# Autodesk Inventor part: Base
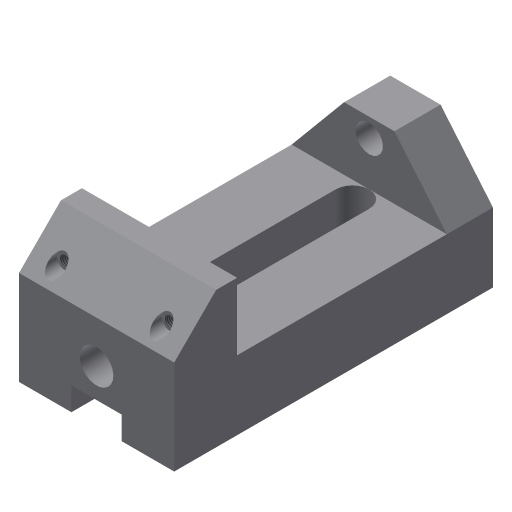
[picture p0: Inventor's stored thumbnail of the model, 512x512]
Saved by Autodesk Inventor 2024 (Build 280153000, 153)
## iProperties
Shininess: 77.0
Length Units: 11269
Angle Units: 11279
Time Units: 11290
Mass Units: 11283
Length Display Precision: 3
Angle Display Precision: 2
Created: 2002-02
Part Number: Base
Document SubType Name: Modeling
Designer: ***
Density: 1 g/cm^3
Material: Generic
Appearance: Default
Density: 0.0
Volumn: 0.0
Area: 0.0
PropertySet Name: Model Information
Control State: 0
Master: False
Checked Out: False
Author: ***
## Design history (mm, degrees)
sketch "Sketch2"
  geometry: L1 (-63.961, -4.254)-(-63.961, -37.254); L2 (-63.961, -37.254)-(88.039, -37.254); L3 (88.039, -37.254)-(88.039, 7.746); L4 (88.039, 7.746)-(68.039, 27.746); L5 (68.039, 27.746)-(58.039, 27.746); L6 (58.039, 27.746)-(58.039, -4.254); L7 (58.039, -4.254)-(-63.961, -4.254)
  constraints: 14 end point, 4 parallel, 1 perpendicular, 1 vertical
  dimensions: "d7" = 10 distance of L4.end L5.end; "d8" = 135 deg angle of L3 L4; "d9" = 33 distance of L1.start L1.end; "d10" = 152 distance of L1.end L2.end; "d11" = 65 distance between parallel lines of L5 L2; "d21" = 30 distance between parallel lines of L3 L6
extrude "Extrusion1" new body sketch "Sketch2" stored distance "d13" = 74; taper "d14" = 0 deg
sketch "Sketch3"
  geometry: L1 (0, 74)-(0, 0) reference; L2 (0, 0)-(-30, 25); L3 (-30, 25)-(-30, 49); L4 (-30, 49)-(0, 74); C1 r 6.5 at (-21, 37)
  constraints: 6 end point, 1 centre point, 1 equal length, 1 parallel
  dimensions: "d15" = 24 distance of L2.end L3.end; "d16" = 30 distance between parallel lines of L3 L1; "d17" = 13 diameter of C1; "d18" = 9 distance from line of L3 C1.centre
extrude "Extrusion2" join sketch "Sketch3" distance "d19" = 22; taper "d20" = 0 deg
sketch "Sketch4"
  geometry: L1 (0, 0)-(0, 74) reference; L2 (0, 0)-(45, 0) reference; C1 r 8 at (25, 37)
  constraints: 1 centre point
  dimensions: "d22" = 16 diameter of C1; "d23" = 25 distance from line of L1 C1.centre; "d24" = 37 distance from line of L2 C1.centre
extrude "Extrusion3" cut sketch "Sketch4" distance "d25" = 13; taper "d26" = 0 deg
sketch "Sketch5"
  geometry: L1 (45, 74)-(0, 74) reference; L2 (65, 0)-(65, 74) reference; 1 further point
  dimensions: "d27" = 12 distance from line of point (51, 62) L1; "d28" = 14 distance from line of L2 point (51, 62)
hole "Hole1" sketch "Sketch5" diameter "d29" = 4.917; stored, may be unused: countersink angle "d33" = 82 deg, drill point angle "d35" = 0 deg; dims "d30" = 12, "d31" = 8, "d32" = 10, "d34" = 45
mirror "Mirror1"
sketch "Sketch6"
  geometry: L1 (100, 0)-(100, 74) reference; L2 (100, 74)-(0, 74) reference; L3 (14, 45)-(92, 45); L4 (92, 29)-(14, 29); A1 r 8 centre (92, 37) between (92, 29) and (92, 45); A2 r 8 centre (14, 37) between (14, 45) and (14, 29)
  constraints: 4 end point, 4 point on circle, 4 tangent, 2 centre point, 1 horizontal, 1 parallel
  dimensions: "d36" = 8 radius of A2; "d37" = 78 distance of L4.start L4.end; "d38" = 8 distance from line of L1 A1.centre; "d39" = 37 distance from line of L2 A2.centre
extrude "Extrusion4" cut sketch "Sketch6" extent not by distance; stored distance "d40" = 13; taper "d41" = 0 deg
sketch "Sketch7"
  geometry: L1 (45, 74)-(0, 74) reference; L2 (11, 49)-(0, 49); L3 (0, 49)-(0, 25); L4 (0, 25)-(11, 25); L5 (11, 25)-(11, 49); L6 (0, 0)-(45, 0) reference; L7 (0, 0)-(0, 74) reference
  constraints: 8 end point, 2 parallel, 1 collinear, 1 horizontal, 1 perpendicular
  dimensions: "d47" = 11 distance of L3.end L4.end; "d48" = 25 distance between parallel lines of L6 L4; "d49" = 24 distance of L2.end L3.end
extrude "Extrusion5" cut sketch "Sketch7" extent not by distance; stored distance "d45" = 13; taper "d46" = 0 deg
body "Solid1"
